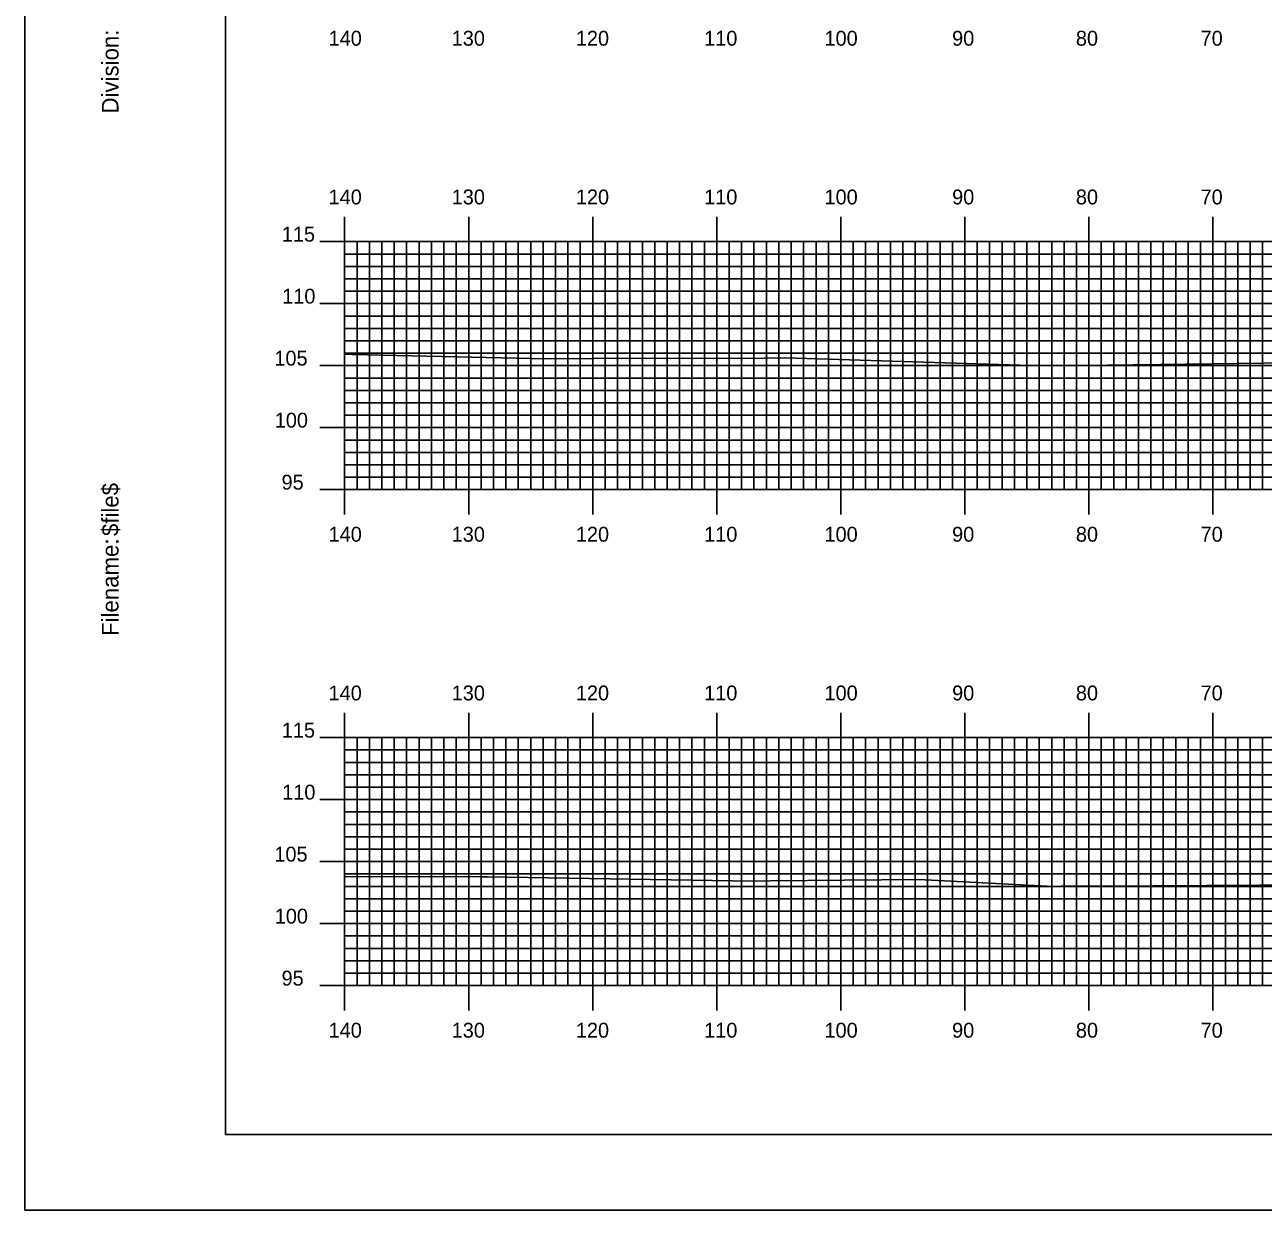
# Model space of a CAD drawing. Extents: x 1779106 to 1779449, y 442591 to 442811.
# Drawn here: x 1779105.5 to 1779205.4, y 442590.5 to 442686.2 of the extents above; entities that cross this region are included whole.
import ezdxf

# ---------------------------------------------------------------- set-up
doc = ezdxf.new("R2010")
doc.units = 0
for name, color, linetype in [('BORDER', 7, 'Continuous'), ('H_V ANNOTATION', 7, 'Continuous'), ('MAJOR', 7, 'Continuous'), ('MINOR', 7, 'Continuous'), ('PLOT BOUNDARY', 7, 'Continuous'), ('S_Roadway_Centerline', 7, 'Continuous')]:
    doc.layers.add(name, color=color, linetype=linetype)

msp = doc.modelspace()

# ---------------------------------------------------------------- linework, layer by layer
at = {"layer": 'BORDER'}
msp.add_lwpolyline([(1779121.729, 442596.665), (1779441.729, 442596.665), (1779441.729, 442806.665), (1779121.729, 442806.665)], close=True, dxfattribs=at)
at = {"layer": 'MAJOR'}
for p, q in [((1779131.329, 442670.669), (1779131.329, 442668.665)), ((1779141.329, 442670.669), (1779141.329, 442668.665)), ((1779151.329, 442670.669), (1779151.329, 442668.665)), ((1779161.329, 442670.669), (1779161.329, 442668.665)), ((1779171.329, 442670.669), (1779171.329, 442668.665)), ((1779181.329, 442670.669), (1779181.329, 442668.665)), ((1779191.329, 442670.669), (1779191.329, 442668.665)), ((1779201.329, 442670.669), (1779201.329, 442668.665)), ((1779129.325, 442668.665), (1779131.329, 442668.665)), ((1779131.329, 442668.665), (1779411.329, 442668.665)), ((1779131.329, 442648.665), (1779131.329, 442668.665)), ((1779131.329, 442648.665), (1779131.329, 442668.665)), ((1779131.329, 442668.665), (1779411.329, 442668.665)), ((1779141.329, 442648.665), (1779141.329, 442668.665)), ((1779151.329, 442648.665), (1779151.329, 442668.665)), ((1779161.329, 442648.665), (1779161.329, 442668.665)), ((1779171.329, 442648.665), (1779171.329, 442668.665)), ((1779181.329, 442648.665), (1779181.329, 442668.665)), ((1779191.329, 442648.665), (1779191.329, 442668.665)), ((1779201.329, 442648.665), (1779201.329, 442668.665)), ((1779129.325, 442663.665), (1779131.329, 442663.665)), ((1779131.329, 442663.665), (1779411.329, 442663.665)), ((1779129.325, 442658.665), (1779131.329, 442658.665)), ((1779131.329, 442658.665), (1779411.329, 442658.665)), ((1779129.325, 442653.665), (1779131.329, 442653.665)), ((1779131.329, 442653.665), (1779411.329, 442653.665)), ((1779129.325, 442648.665), (1779131.329, 442648.665)), ((1779131.329, 442648.665), (1779411.329, 442648.665)), ((1779131.329, 442648.665), (1779411.329, 442648.665)), ((1779131.329, 442646.661), (1779131.329, 442648.665)), ((1779141.329, 442646.661), (1779141.329, 442648.665)), ((1779151.329, 442646.661), (1779151.329, 442648.665)), ((1779161.329, 442646.661), (1779161.329, 442648.665)), ((1779171.329, 442646.661), (1779171.329, 442648.665)), ((1779181.329, 442646.661), (1779181.329, 442648.665)), ((1779191.329, 442646.661), (1779191.329, 442648.665)), ((1779201.329, 442646.661), (1779201.329, 442648.665)), ((1779131.329, 442630.669), (1779131.329, 442628.665)), ((1779141.329, 442630.669), (1779141.329, 442628.665)), ((1779151.329, 442630.669), (1779151.329, 442628.665)), ((1779161.329, 442630.669), (1779161.329, 442628.665)), ((1779171.329, 442630.669), (1779171.329, 442628.665)), ((1779181.329, 442630.669), (1779181.329, 442628.665)), ((1779191.329, 442630.669), (1779191.329, 442628.665)), ((1779201.329, 442630.669), (1779201.329, 442628.665)), ((1779129.325, 442628.665), (1779131.329, 442628.665)), ((1779131.329, 442628.665), (1779411.329, 442628.665)), ((1779131.329, 442608.665), (1779131.329, 442628.665)), ((1779131.329, 442608.665), (1779131.329, 442628.665)), ((1779131.329, 442628.665), (1779411.329, 442628.665)), ((1779141.329, 442608.665), (1779141.329, 442628.665)), ((1779151.329, 442608.665), (1779151.329, 442628.665)), ((1779161.329, 442608.665), (1779161.329, 442628.665)), ((1779171.329, 442608.665), (1779171.329, 442628.665)), ((1779181.329, 442608.665), (1779181.329, 442628.665)), ((1779191.329, 442608.665), (1779191.329, 442628.665)), ((1779201.329, 442608.665), (1779201.329, 442628.665)), ((1779129.325, 442623.665), (1779131.329, 442623.665)), ((1779131.329, 442623.665), (1779411.329, 442623.665)), ((1779129.325, 442618.665), (1779131.329, 442618.665)), ((1779131.329, 442618.665), (1779411.329, 442618.665)), ((1779129.325, 442613.665), (1779131.329, 442613.665)), ((1779131.329, 442613.665), (1779411.329, 442613.665)), ((1779129.325, 442608.665), (1779131.329, 442608.665)), ((1779131.329, 442608.665), (1779411.329, 442608.665)), ((1779131.329, 442608.665), (1779411.329, 442608.665)), ((1779131.329, 442606.661), (1779131.329, 442608.665)), ((1779141.329, 442606.661), (1779141.329, 442608.665)), ((1779151.329, 442606.661), (1779151.329, 442608.665)), ((1779161.329, 442606.661), (1779161.329, 442608.665)), ((1779171.329, 442606.661), (1779171.329, 442608.665)), ((1779181.329, 442606.661), (1779181.329, 442608.665)), ((1779191.329, 442606.661), (1779191.329, 442608.665)), ((1779201.329, 442606.661), (1779201.329, 442608.665))]:
    msp.add_line(p, q, dxfattribs=at)
at = {"layer": 'MINOR'}
for p, q in [((1779132.329, 442648.665), (1779132.329, 442668.665)), ((1779133.329, 442648.665), (1779133.329, 442668.665)), ((1779134.329, 442648.665), (1779134.329, 442668.665)), ((1779135.329, 442648.665), (1779135.329, 442668.665)), ((1779136.329, 442648.665), (1779136.329, 442668.665)), ((1779137.329, 442648.665), (1779137.329, 442668.665)), ((1779138.329, 442648.665), (1779138.329, 442668.665)), ((1779139.329, 442648.665), (1779139.329, 442668.665)), ((1779140.329, 442648.665), (1779140.329, 442668.665)), ((1779142.329, 442648.665), (1779142.329, 442668.665)), ((1779143.329, 442648.665), (1779143.329, 442668.665)), ((1779144.329, 442648.665), (1779144.329, 442668.665)), ((1779145.329, 442648.665), (1779145.329, 442668.665)), ((1779146.329, 442648.665), (1779146.329, 442668.665)), ((1779147.329, 442648.665), (1779147.329, 442668.665)), ((1779148.329, 442648.665), (1779148.329, 442668.665)), ((1779149.329, 442648.665), (1779149.329, 442668.665)), ((1779150.329, 442648.665), (1779150.329, 442668.665)), ((1779152.329, 442648.665), (1779152.329, 442668.665)), ((1779153.329, 442648.665), (1779153.329, 442668.665)), ((1779154.329, 442648.665), (1779154.329, 442668.665)), ((1779155.329, 442648.665), (1779155.329, 442668.665)), ((1779156.329, 442648.665), (1779156.329, 442668.665)), ((1779157.329, 442648.665), (1779157.329, 442668.665)), ((1779158.329, 442648.665), (1779158.329, 442668.665)), ((1779159.329, 442648.665), (1779159.329, 442668.665)), ((1779160.329, 442648.665), (1779160.329, 442668.665)), ((1779162.329, 442648.665), (1779162.329, 442668.665)), ((1779163.329, 442648.665), (1779163.329, 442668.665)), ((1779164.329, 442648.665), (1779164.329, 442668.665)), ((1779165.329, 442648.665), (1779165.329, 442668.665)), ((1779166.329, 442648.665), (1779166.329, 442668.665)), ((1779167.329, 442648.665), (1779167.329, 442668.665)), ((1779168.329, 442648.665), (1779168.329, 442668.665)), ((1779169.329, 442648.665), (1779169.329, 442668.665)), ((1779170.329, 442648.665), (1779170.329, 442668.665)), ((1779172.329, 442648.665), (1779172.329, 442668.665)), ((1779173.329, 442648.665), (1779173.329, 442668.665)), ((1779174.329, 442648.665), (1779174.329, 442668.665)), ((1779175.329, 442648.665), (1779175.329, 442668.665)), ((1779176.329, 442648.665), (1779176.329, 442668.665)), ((1779177.329, 442648.665), (1779177.329, 442668.665)), ((1779178.329, 442648.665), (1779178.329, 442668.665)), ((1779179.329, 442648.665), (1779179.329, 442668.665)), ((1779180.329, 442648.665), (1779180.329, 442668.665)), ((1779182.329, 442648.665), (1779182.329, 442668.665)), ((1779183.329, 442648.665), (1779183.329, 442668.665)), ((1779184.329, 442648.665), (1779184.329, 442668.665)), ((1779185.329, 442648.665), (1779185.329, 442668.665)), ((1779186.329, 442648.665), (1779186.329, 442668.665)), ((1779187.329, 442648.665), (1779187.329, 442668.665)), ((1779188.329, 442648.665), (1779188.329, 442668.665)), ((1779189.329, 442648.665), (1779189.329, 442668.665)), ((1779190.329, 442648.665), (1779190.329, 442668.665)), ((1779192.329, 442648.665), (1779192.329, 442668.665)), ((1779193.329, 442648.665), (1779193.329, 442668.665)), ((1779194.329, 442648.665), (1779194.329, 442668.665)), ((1779195.329, 442648.665), (1779195.329, 442668.665)), ((1779196.329, 442648.665), (1779196.329, 442668.665)), ((1779197.329, 442648.665), (1779197.329, 442668.665)), ((1779198.329, 442648.665), (1779198.329, 442668.665)), ((1779199.329, 442648.665), (1779199.329, 442668.665)), ((1779200.329, 442648.665), (1779200.329, 442668.665)), ((1779202.329, 442648.665), (1779202.329, 442668.665)), ((1779203.329, 442648.665), (1779203.329, 442668.665)), ((1779204.329, 442648.665), (1779204.329, 442668.665)), ((1779205.329, 442648.665), (1779205.329, 442668.665)), ((1779131.329, 442667.665), (1779411.329, 442667.665)), ((1779131.329, 442667.665), (1779133.333, 442667.665)), ((1779131.329, 442666.665), (1779411.329, 442666.665)), ((1779131.329, 442666.665), (1779133.333, 442666.665)), ((1779131.329, 442665.665), (1779411.329, 442665.665)), ((1779131.329, 442665.665), (1779133.333, 442665.665)), ((1779131.329, 442664.665), (1779411.329, 442664.665)), ((1779131.329, 442664.665), (1779133.333, 442664.665)), ((1779131.329, 442662.665), (1779411.329, 442662.665)), ((1779131.329, 442662.665), (1779133.333, 442662.665)), ((1779131.329, 442661.665), (1779411.329, 442661.665)), ((1779131.329, 442661.665), (1779133.333, 442661.665)), ((1779131.329, 442660.665), (1779411.329, 442660.665)), ((1779131.329, 442660.665), (1779133.333, 442660.665)), ((1779131.329, 442659.665), (1779411.329, 442659.665)), ((1779131.329, 442659.665), (1779133.333, 442659.665)), ((1779131.329, 442657.665), (1779411.329, 442657.665)), ((1779131.329, 442657.665), (1779133.333, 442657.665)), ((1779131.329, 442656.665), (1779411.329, 442656.665)), ((1779131.329, 442656.665), (1779133.333, 442656.665)), ((1779131.329, 442655.665), (1779411.329, 442655.665)), ((1779131.329, 442655.665), (1779133.333, 442655.665)), ((1779131.329, 442654.665), (1779411.329, 442654.665)), ((1779131.329, 442654.665), (1779133.333, 442654.665)), ((1779131.329, 442652.665), (1779411.329, 442652.665)), ((1779131.329, 442652.665), (1779133.333, 442652.665)), ((1779131.329, 442651.665), (1779411.329, 442651.665)), ((1779131.329, 442651.665), (1779133.333, 442651.665)), ((1779131.329, 442650.665), (1779411.329, 442650.665)), ((1779131.329, 442650.665), (1779133.333, 442650.665)), ((1779131.329, 442649.665), (1779411.329, 442649.665)), ((1779131.329, 442649.665), (1779133.333, 442649.665)), ((1779132.329, 442608.665), (1779132.329, 442628.665)), ((1779133.329, 442608.665), (1779133.329, 442628.665)), ((1779134.329, 442608.665), (1779134.329, 442628.665)), ((1779135.329, 442608.665), (1779135.329, 442628.665)), ((1779136.329, 442608.665), (1779136.329, 442628.665)), ((1779137.329, 442608.665), (1779137.329, 442628.665)), ((1779138.329, 442608.665), (1779138.329, 442628.665)), ((1779139.329, 442608.665), (1779139.329, 442628.665)), ((1779140.329, 442608.665), (1779140.329, 442628.665)), ((1779142.329, 442608.665), (1779142.329, 442628.665)), ((1779143.329, 442608.665), (1779143.329, 442628.665)), ((1779144.329, 442608.665), (1779144.329, 442628.665)), ((1779145.329, 442608.665), (1779145.329, 442628.665)), ((1779146.329, 442608.665), (1779146.329, 442628.665)), ((1779147.329, 442608.665), (1779147.329, 442628.665)), ((1779148.329, 442608.665), (1779148.329, 442628.665)), ((1779149.329, 442608.665), (1779149.329, 442628.665)), ((1779150.329, 442608.665), (1779150.329, 442628.665)), ((1779152.329, 442608.665), (1779152.329, 442628.665)), ((1779153.329, 442608.665), (1779153.329, 442628.665)), ((1779154.329, 442608.665), (1779154.329, 442628.665)), ((1779155.329, 442608.665), (1779155.329, 442628.665)), ((1779156.329, 442608.665), (1779156.329, 442628.665)), ((1779157.329, 442608.665), (1779157.329, 442628.665)), ((1779158.329, 442608.665), (1779158.329, 442628.665)), ((1779159.329, 442608.665), (1779159.329, 442628.665)), ((1779160.329, 442608.665), (1779160.329, 442628.665)), ((1779162.329, 442608.665), (1779162.329, 442628.665)), ((1779163.329, 442608.665), (1779163.329, 442628.665)), ((1779164.329, 442608.665), (1779164.329, 442628.665)), ((1779165.329, 442608.665), (1779165.329, 442628.665)), ((1779166.329, 442608.665), (1779166.329, 442628.665)), ((1779167.329, 442608.665), (1779167.329, 442628.665)), ((1779168.329, 442608.665), (1779168.329, 442628.665)), ((1779169.329, 442608.665), (1779169.329, 442628.665)), ((1779170.329, 442608.665), (1779170.329, 442628.665)), ((1779172.329, 442608.665), (1779172.329, 442628.665)), ((1779173.329, 442608.665), (1779173.329, 442628.665)), ((1779174.329, 442608.665), (1779174.329, 442628.665)), ((1779175.329, 442608.665), (1779175.329, 442628.665)), ((1779176.329, 442608.665), (1779176.329, 442628.665)), ((1779177.329, 442608.665), (1779177.329, 442628.665)), ((1779178.329, 442608.665), (1779178.329, 442628.665)), ((1779179.329, 442608.665), (1779179.329, 442628.665)), ((1779180.329, 442608.665), (1779180.329, 442628.665)), ((1779182.329, 442608.665), (1779182.329, 442628.665)), ((1779183.329, 442608.665), (1779183.329, 442628.665)), ((1779184.329, 442608.665), (1779184.329, 442628.665)), ((1779185.329, 442608.665), (1779185.329, 442628.665)), ((1779186.329, 442608.665), (1779186.329, 442628.665)), ((1779187.329, 442608.665), (1779187.329, 442628.665)), ((1779188.329, 442608.665), (1779188.329, 442628.665)), ((1779189.329, 442608.665), (1779189.329, 442628.665)), ((1779190.329, 442608.665), (1779190.329, 442628.665)), ((1779192.329, 442608.665), (1779192.329, 442628.665)), ((1779193.329, 442608.665), (1779193.329, 442628.665)), ((1779194.329, 442608.665), (1779194.329, 442628.665)), ((1779195.329, 442608.665), (1779195.329, 442628.665)), ((1779196.329, 442608.665), (1779196.329, 442628.665)), ((1779197.329, 442608.665), (1779197.329, 442628.665)), ((1779198.329, 442608.665), (1779198.329, 442628.665)), ((1779199.329, 442608.665), (1779199.329, 442628.665)), ((1779200.329, 442608.665), (1779200.329, 442628.665)), ((1779202.329, 442608.665), (1779202.329, 442628.665)), ((1779203.329, 442608.665), (1779203.329, 442628.665)), ((1779204.329, 442608.665), (1779204.329, 442628.665)), ((1779205.329, 442608.665), (1779205.329, 442628.665)), ((1779131.329, 442627.665), (1779411.329, 442627.665)), ((1779131.329, 442627.665), (1779133.333, 442627.665)), ((1779131.329, 442626.665), (1779411.329, 442626.665)), ((1779131.329, 442626.665), (1779133.333, 442626.665)), ((1779131.329, 442625.665), (1779411.329, 442625.665)), ((1779131.329, 442625.665), (1779133.333, 442625.665)), ((1779131.329, 442624.665), (1779411.329, 442624.665)), ((1779131.329, 442624.665), (1779133.333, 442624.665)), ((1779131.329, 442622.665), (1779411.329, 442622.665)), ((1779131.329, 442622.665), (1779133.333, 442622.665)), ((1779131.329, 442621.665), (1779411.329, 442621.665)), ((1779131.329, 442621.665), (1779133.333, 442621.665)), ((1779131.329, 442620.665), (1779411.329, 442620.665)), ((1779131.329, 442620.665), (1779133.333, 442620.665)), ((1779131.329, 442619.665), (1779411.329, 442619.665)), ((1779131.329, 442619.665), (1779133.333, 442619.665)), ((1779131.329, 442617.665), (1779411.329, 442617.665)), ((1779131.329, 442617.665), (1779133.333, 442617.665)), ((1779131.329, 442616.665), (1779411.329, 442616.665)), ((1779131.329, 442616.665), (1779133.333, 442616.665)), ((1779131.329, 442615.665), (1779411.329, 442615.665)), ((1779131.329, 442615.665), (1779133.333, 442615.665)), ((1779131.329, 442614.665), (1779411.329, 442614.665)), ((1779131.329, 442614.665), (1779133.333, 442614.665)), ((1779131.329, 442612.665), (1779411.329, 442612.665)), ((1779131.329, 442612.665), (1779133.333, 442612.665)), ((1779131.329, 442611.665), (1779411.329, 442611.665)), ((1779131.329, 442611.665), (1779133.333, 442611.665)), ((1779131.329, 442610.665), (1779411.329, 442610.665)), ((1779131.329, 442610.665), (1779133.333, 442610.665)), ((1779131.329, 442609.665), (1779411.329, 442609.665)), ((1779131.329, 442609.665), (1779133.333, 442609.665))]:
    msp.add_line(p, q, dxfattribs=at)
at = {"layer": 'PLOT BOUNDARY'}
msp.add_lwpolyline([(1779105.542, 442590.547), (1779445.542, 442590.547), (1779445.542, 442810.547), (1779105.542, 442810.547)], close=True, dxfattribs=at)
at = {"layer": 'S_Roadway_Centerline'}
for points in [[(1779131.329, 442659.583), (1779131.944, 442659.562), (1779147.54, 442659.22), (1779155.296, 442659.256), (1779163.445, 442659.245), (1779166.868, 442659.299), (1779187.492, 442658.648), (1779190.733, 442658.669), (1779209.659, 442658.921)], [(1779131.329, 442617.466), (1779142.255, 442617.446), (1779142.826, 442617.444), (1779164.226, 442617.094), (1779165.647, 442617.112), (1779177.631, 442617.221), (1779188.484, 442616.665), (1779189.077, 442616.677), (1779192.273, 442616.677), (1779209.36, 442616.778)]]:
    msp.add_lwpolyline(points, dxfattribs=at)

# ---------------------------------------------------------------- texts
at = {"layer": 'BORDER'}
for s, p in [('Division:', (1779113.099, 442678.997)), ('$file$', (1779113.099, 442644.916)), ('Filename:', (1779113.099, 442636.862))]:
    msp.add_text(s, height=1.3392, rotation=90, dxfattribs=at).set_placement(p)
at = {"layer": 'H_V ANNOTATION'}
for s, p in [('140', (1779130.034, 442684.465)), ('130', (1779139.959, 442684.465)), ('120', (1779149.97, 442684.465)), ('110', (1779160.312, 442684.465)), ('100', (1779170.013, 442684.465)), ('90', (1779180.301, 442684.465)), ('80', (1779190.28, 442684.465)), ('70', (1779200.333, 442684.465)), ('140', (1779130.034, 442671.665)), ('130', (1779139.959, 442671.665)), ('120', (1779149.97, 442671.665)), ('110', (1779160.312, 442671.665)), ('100', (1779170.013, 442671.665)), ('90', (1779180.301, 442671.665)), ('80', (1779190.28, 442671.665)), ('70', (1779200.333, 442671.665)), ('115', (1779126.264, 442668.665)), ('110', (1779126.296, 442663.665)), ('105', (1779125.664, 442658.665)), ('100', (1779125.696, 442653.665)), ('95', (1779126.242, 442648.665)), ('140', (1779130.034, 442644.465)), ('130', (1779139.959, 442644.465)), ('120', (1779149.97, 442644.465)), ('110', (1779160.312, 442644.465)), ('100', (1779170.013, 442644.465)), ('90', (1779180.301, 442644.465)), ('80', (1779190.28, 442644.465)), ('70', (1779200.333, 442644.465)), ('140', (1779130.034, 442631.665)), ('130', (1779139.959, 442631.665)), ('120', (1779149.97, 442631.665)), ('110', (1779160.312, 442631.665)), ('100', (1779170.013, 442631.665)), ('90', (1779180.301, 442631.665)), ('80', (1779190.28, 442631.665)), ('70', (1779200.333, 442631.665)), ('115', (1779126.264, 442628.665)), ('110', (1779126.296, 442623.665)), ('105', (1779125.664, 442618.665)), ('100', (1779125.696, 442613.665)), ('95', (1779126.242, 442608.665)), ('140', (1779130.034, 442604.465)), ('130', (1779139.959, 442604.465)), ('120', (1779149.97, 442604.465)), ('110', (1779160.312, 442604.465)), ('100', (1779170.013, 442604.465)), ('90', (1779180.301, 442604.465)), ('80', (1779190.28, 442604.465)), ('70', (1779200.333, 442604.465))]:
    msp.add_text(s, height=1.2, dxfattribs=at).set_placement(p)
at = {"layer": 'MAJOR'}
for p in [(1779131.32, 442648.665), (1779131.32, 442608.665)]:
    msp.add_text('-', height=0.012, dxfattribs=at).set_placement(p)

doc.saveas('drawing.dxf')
